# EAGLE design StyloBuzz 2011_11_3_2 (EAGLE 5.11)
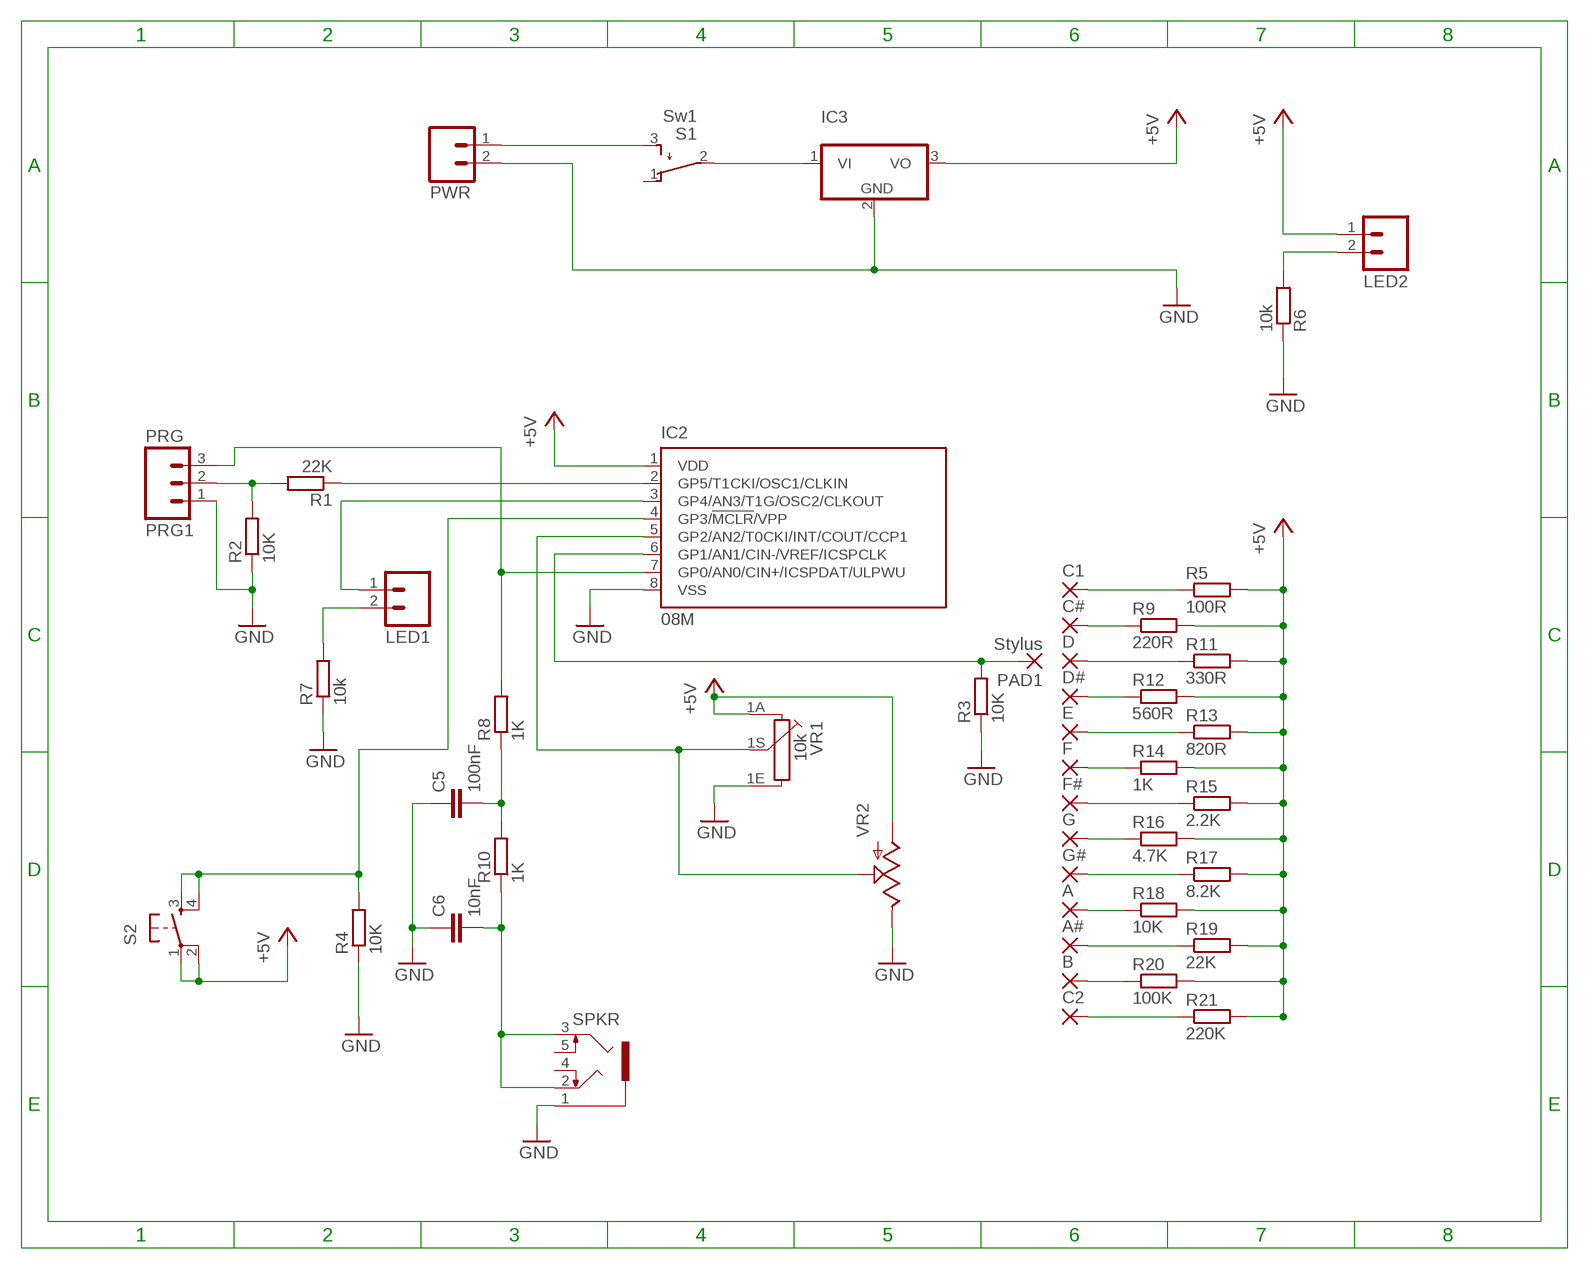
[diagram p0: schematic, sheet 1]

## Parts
A  1,6/0,8  [1,6/0,8]
A#  1,6/0,8  [1,6/0,8]
B  1,6/0,8  [1,6/0,8]
C1  1,6/0,8  [1,6/0,8]
C2  1,6/0,8  [1,6/0,8]
C5  100nF  C5/2.5  [C5B2.5]
C6  10nF  C5/2.5  [C5B2.5]
C#  1,6/0,8  [1,6/0,8]
D  1,6/0,8  [1,6/0,8]
D#  1,6/0,8  [1,6/0,8]
E  1,6/0,8  [1,6/0,8]
F  1,6/0,8  [1,6/0,8]
F#  1,6/0,8  [1,6/0,8]
G  1,6/0,8  [1,6/0,8]
G#  1,6/0,8  [1,6/0,8]
IC2  08M  PIC12F683P  [DIL8]
IC3  786TV  [TO220V]
LED1  M02  [02P]
LED2  M02  [02P]
PAD1  Stylus  3,81/1,4  [3,81/1,4]
PRG  PRG1  M03  [03P]
PWR  M02  [02P]
R1  22K  R-EU_0207/10  [0207/10]
R2  10K  R-EU_0207/10  [0207/10]
R3  10K  R-EU_0207/10  [0207/10]
R4  10K  R-EU_0207/10  [0207/10]
R5  100R  R-EU_0207/10  [0207/10]
R6  10k  R-EU_0207/10  [0207/10]
R7  10k  R-EU_0207/10  [0207/10]
R8  1K  R-EU_0207/10  [0207/10]
R9  220R  R-EU_0207/10  [0207/10]
R10  1K  R-EU_0207/10  [0207/10]
R11  330R  R-EU_0207/10  [0207/10]
R12  560R  R-EU_0207/10  [0207/10]
R13  820R  R-EU_0207/10  [0207/10]
R14  1K  R-EU_0207/10  [0207/10]
R15  2.2K  R-EU_0207/10  [0207/10]
R16  4.7K  R-EU_0207/10  [0207/10]
R17  8.2K  R-EU_0207/10  [0207/10]
R18  10K  R-EU_0207/10  [0207/10]
R19  22K  R-EU_0207/10  [0207/10]
R20  100K  R-EU_0207/10  [0207/10]
R21  220K  R-EU_0207/10  [0207/10]
S1  Sw1  TL32YO  [TL3XYO]
S2  TAC_SWITCHPTH  [TACTILE-PTH]
SPKR  1503_09  [1503_09]
VR1  10k  PC16S  [PC16S]
VR2  POT  [ALPS_POT]

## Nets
+5V: IC2.1(VDD) IC3.3(VO) LED2.1 R5.2 R9.2 R11.2 R12.2 R13.2 R14.2 R15.2 R16.2 R17.2 R18.2 R19.2 R20.2 R21.2 S2.1 S2.2 VR1.1A VR2.P$3(A)
N$1: PWR.1 S1.3(S)
N$2: IC3.1(VI) S1.2(P)
N$3: IC2.2(GP5/T1CKI/OSC1/CLKIN) R1.1
N$4: C1.1(P) R5.1
N$5: IC2.4(GP3/!MCLR!/VPP) R4.2 S2.3 S2.4
N$6: IC2.7(GP0/AN0/CIN+/ICSPDAT/ULPWU) PRG.3 R8.2
N$7: IC2.3(GP4/AN3/T1G/OSC2/CLKOUT) LED1.1
N$8: C#.1(P) R9.1
N$9: IC2.6(GP1/AN1/CIN-/VREF/ICSPCLK) PAD1.1(P) R3.2
N$10: LED1.2 R7.2
N$11: C5.2 R8.1 R10.2
N$12: C6.2 R10.1 SPKR.2 SPKR.3
N$13: IC2.5(GP2/AN2/T0CKI/INT/COUT/CCP1) VR1.1S VR2.P$2(S)
N$14: D.1(P) R11.1
N$15: D#.1(P) R12.1
N$16: LED2.2 R6.2
N$17: E.1(P) R13.1
N$18: F.1(P) R14.1
N$19: F#.1(P) R15.1
N$20: G.1(P) R16.1
N$21: G#.1(P) R17.1
N$22: A.1(P) R18.1
N$23: A#.1(P) R19.1
N$24: B.1(P) R20.1
N$25: C2.1(P) R21.1
N$26: PRG.2 R1.2 R2.2
N$28: C5.1 C6.1 IC2.8(VSS) IC3.2(GND) PRG.1 PWR.2 R2.1 R3.1 R4.1 R6.1 R7.1 SPKR.1 VR1.1E VR2.P$1(E) ; supply symbol labelled GND
Unconnected: S1.1(O) SPKR.4 SPKR.5

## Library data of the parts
A A# B C1 C2 C# D D# E F F# G G# = wirepad:1,6/0,8: THROUGH-HOLE PAD
C5 C6 = capacitor-wima:C: CAPACITOR
IC2 = microchip:PIC12F683: 8-Pin Flash-Based, 8-Bit CMOS Microcontrollers with nanoWatt Technology Source: http://ww1.microchip.com/downloads/en/DeviceDoc/41211D_.pdf; MF: MICROCHIP; MPN: PIC12F683-I/P; OC_FARNELL: 9759034; OC_NEWARK: 89H0442
IC3 = linear:78*: Positive VOLTAGE REGULATOR Source: http://cache.national.com/ds/LM/LM78L05.pdf http://www.fairchildsemi.com/ds/LM/LM7805.pdf
LED1 LED2 PWR = con-amp-quick:M02: AMP QUICK CONNECTOR; OC_FARNELL: unknown; OC_NEWARK: unknown
PAD1 = wirepad:3,81/1,4: THROUGH-HOLE PAD
PRG = con-amp-quick:M03: AMP QUICK CONNECTOR; OC_FARNELL: unknown; OC_NEWARK: unknown
R1-R21 = resistor2:R-EU_: RESISTOR, European symbol
S1 = switch:TL32YO: TINY SWITCH ON - MOM Source: http://www2.produktinfo.conrad.com/datenblaetter/700000-724999/705152-da-01-de-Subminiaturschalter_TL_36YO.pdf
S2 = SparkFun:TAC_SWITCH: Momentary Switch Button commonly used for reset or general input. Spark Fun Electronics SKU : COM-00097
SPKR = con-lumberg:1503_09: Jack connectors according to JISC 6560, 3.5 mm Klinkeneinbaukupplung nach JISC 6560, 3,5 mm, 3-polig/ stereo, abgewinkelte Ausführung, mit 2 Öffnern und Lötaugen, für Leiterplatten Rückseitenmontage Source: http://www.lumberg.com/Produkte/PDFs/1503_09.pdf; OC_FARNELL: 1243244; OC_NEWARK: unknown
VR1 = piher:PC16S: POTENTIOMETER single carbon potentiometer, 16 mm, S3ROH; OC_FARNELL: 4452940; OC_NEWARK: unknown
VR2 = SparkFun:POT

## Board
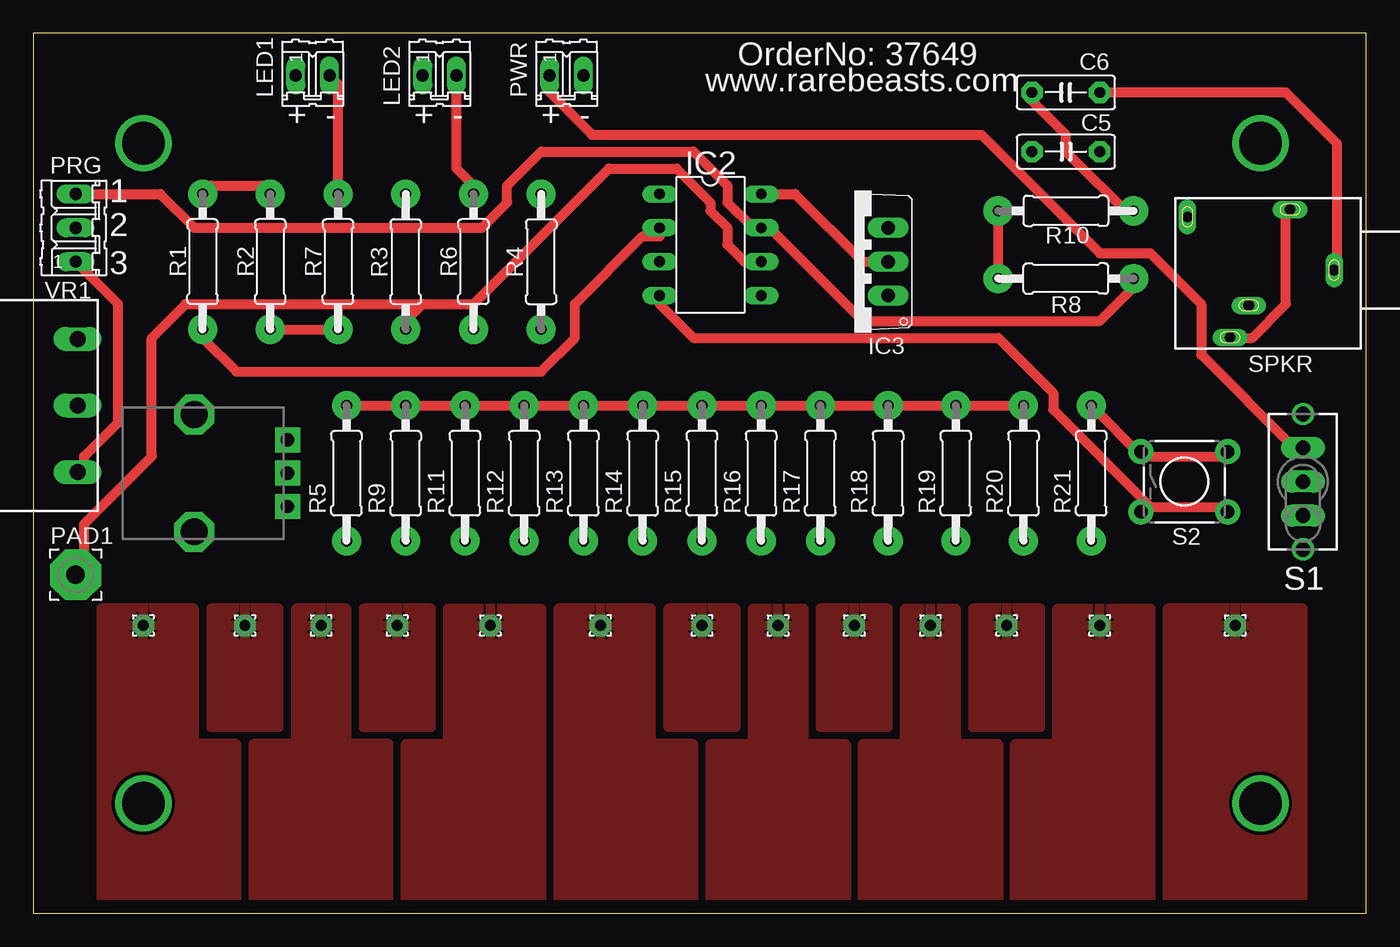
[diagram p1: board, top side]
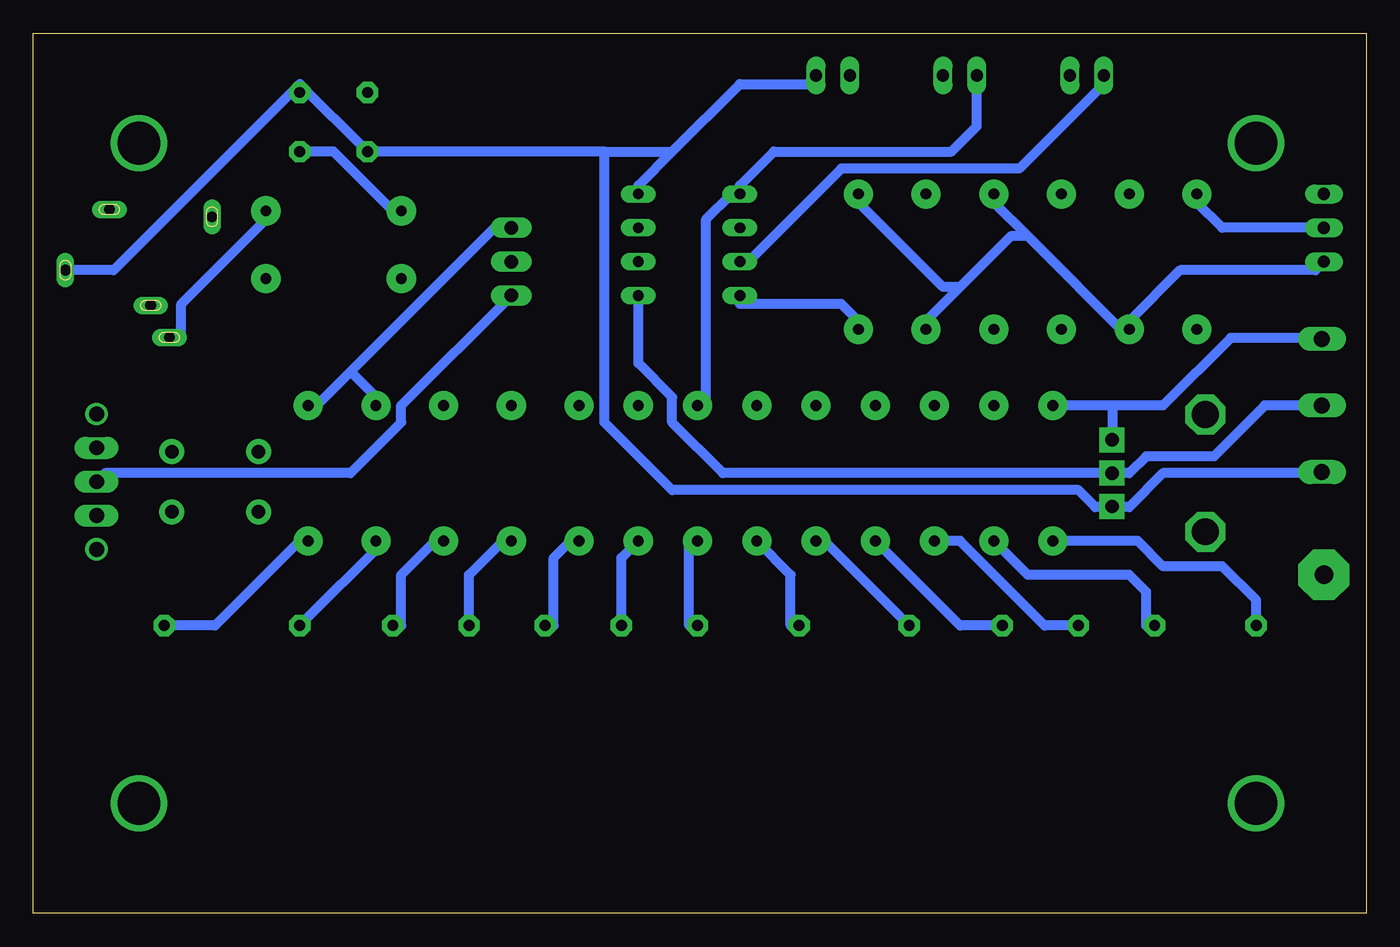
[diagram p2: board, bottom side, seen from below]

Size 100 x 66.03 mm. Coordinates in mm from the lower left corner, seen from the top.
Outline: 0,0 100,0 100,66.03 0,66.03 0,0
Copper layers (1*16): Top 0.035mm / dielectric 1.5mm / Bottom 0.035mm
Design rules "default *": minimum track width 30mil, minimum drill 24mil, track to track 8mil, track to pad 8mil, pad to pad 8mil, via to via 8mil, smd to smd 8mil, copper to edge 40mil, drill to drill 8mil, minimum pad ring 10mil, minimum via ring 8mil, stop-mask expansion 4mil, vias tented up to drill 0mil, thermal gap 10mil

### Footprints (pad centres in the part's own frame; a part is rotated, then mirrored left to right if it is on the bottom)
1,6/0,8 = drill 0.813 pad 1.6 octagon: 1 0,0
C5B2.5 = drill 0.813 pad 1.6 octagon: 1 -2.54,0; 2 2.54,0
DIL8 = drill 0.813 long: 1 -3.81,-3.81; 2 -1.27,-3.81; 3 1.27,-3.81; 4 3.81,-3.81; 5 3.81,3.81; 6 1.27,3.81; 7 -1.27,3.81; 8 -3.81,3.81
TO220V = drill 1.016 long: 1 -2.54,-2.54; 2 0,-2.54; 3 2.54,-2.54
02P = drill 0.914 long: 1 -1.27,0; 2 1.27,0
3,81/1,4 = drill 1.397 pad 3.81 octagon: 1 0,0
03P = drill 0.914 long: 1 -2.54,0; 2 0,0; 3 2.54,0
0207/10 = drill 0.813 pad 2.184 round: 1 -5.08,0; 2 5.08,0
TL3XYO = drill 1.1 pad 1.422 long: 1 -2.54,0; 2 0,0; 3 2.54,0 | drill 1.1 pad 1.676 round: M1 -5.08,0; M2 5.08,0
TACTILE-PTH = drill 1.016 pad 1.88 round: 1 -3.251,2.261; 2 3.251,2.261; 3 -3.251,-2.261; 4 3.251,-2.261
1503_09 = drill 0.8 pad 1.2 long: 1 0,-2.1; 2 -4.55,-5.4; 3 5.05,-9.9; 4 -4,-13.1; 5 2.65,-8.5
PC16S = drill 1.2 long: 1A -5,6.5; 1E 5,6.5; 1S 0,6.5
ALPS_POT = drill 1 pad 1.88 square: P$1 7,-2.5; P$2 7,0; P$3 7,2.5 | drill 2 octagon: P$4 0,-4.4; P$5 0,4.4

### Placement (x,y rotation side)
A  67.31,21.59 0 top
A#  73.03,21.59 0 top
B  80.01,21.59 0 top
C1  8.26,21.59 0 top
C2  90.17,21.59 0 top
C5  77.47,57.15 0 top
C6  77.47,61.59 180 top
C#  15.88,21.59 0 top
D  21.59,21.59 0 top
D#  27.3,21.59 0 top
E  34.29,21.59 0 top
F  42.55,21.59 0 top
F#  50.16,21.59 0 top
G  55.88,21.59 0 top
G#  61.59,21.59 0 top
IC2  50.8,50.16 270 top
IC3  61.59,48.9 90 top
LED1  20.95,62.87 0 top
LED2  30.48,62.87 0 top
PAD1  3.17,25.4 0 top
PRG  3.17,51.44 90 top
PWR  40.01,62.87 0 top
R1  12.7,48.9 90 top
R2  17.78,48.9 90 top
R3  27.94,48.9 270 top
R4  38.1,48.9 270 top
R5  23.5,33.02 90 top
R6  33.02,48.9 90 top
R7  22.86,48.9 90 top
R8  77.47,47.62 0 top
R9  27.94,33.02 90 top
R10  77.47,52.7 180 top
R11  32.38,33.02 90 top
R12  36.83,33.02 90 top
R13  41.27,33.02 90 top
R14  45.72,33.02 90 top
R15  50.16,33.02 90 top
R16  54.61,33.02 90 top
R17  59.05,33.02 90 top
R18  64.14,33.02 90 top
R19  69.22,33.02 90 top
R20  74.3,33.02 90 top
R21  79.38,33.02 90 top
S1  95.25,32.38 90 top
S2  86.36,32.38 0 top
SPKR  99.69,48.26 270 top
VR1  -3.17,38.1 270 top
VR2  12.06,33.02 0 top

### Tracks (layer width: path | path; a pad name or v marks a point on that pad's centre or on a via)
+5V
  Top 0.762: R5.2 R9.2 R11.2 R12.2 R13.2 R14.2 R15.2 R16.2 R17.2 R18.2 R19.2 R20.2 | S2.2 89.53,34.29 83.82,34.29 S2.1 83.19,34.29 R21.2
  Bottom 0.762: VR1.1A 3.81,43.18 10.16,43.18 15.24,38.1 19.05,38.1 | 19.05,38.1 R5.2 | IC3.3 65.41,51.44 76.2,40.64 | 76.2,40.64 78.74,38.1 R21.2 | R15.2 49.53,38.1 49.53,52.07 47.62,53.98 IC2.1 46.99,54.61 44.45,57.15 31.11,57.15 29.21,59.05 LED2.1 | 76.2,40.64 73.66,38.1 R20.2 | 19.05,38.1 19.05,35.56 VR2.P$3
N$1
  Top 0.762: PWR.1 38.73,61.59 41.91,58.42 71.12,58.42 80.01,49.53 83.82,49.53 87.63,45.72 87.63,41.91 94.61,34.92 S1.3
N$2
  Bottom 0.762: IC3.1 72.39,38.1 72.39,36.83 76.2,33.02 94.61,33.02 S1.2
N$3
  Top 0.762: IC2.2 46.99,50.8 45.72,50.8 40.64,45.72 40.64,43.18 38.1,40.64 15.24,40.64 12.7,43.18 R1.1
N$4
  Bottom 0.762: C1.1 8.26,23.5 10.79,26.04 15.24,26.04 17.14,27.94 R5.1
  pour Top (isolate 0.254): 5.08,22.86 5.08,0 15.24,0 15.24,12.7 12.06,12.7 12.06,22.86
N$5
  Top 0.762: 83.82,30.48 88.9,30.48 S2.4 | 83.82,30.48 76.52,37.78 76.52,39.05 72.39,43.18 49.53,43.18 46.99,45.72 IC2.4 | 83.82,30.48 S2.3
  Bottom 0.762: IC2.4 46.99,45.72 39.37,45.72 38.1,44.45 R4.2
N$6
  Top 0.762: R8.2 82.55,46.99 80.01,44.45 62.23,44.45 55.24,51.44 IC2.7 53.98,51.44 52.07,53.34 52.07,54.61 49.53,57.15 38.1,57.15 35.56,54.61 35.56,53.34 33.66,51.44 12.06,51.44 9.53,53.98 PRG.3
N$7
  Bottom 0.762: IC2.3 46.35,48.9 39.37,55.88 26.04,55.88 19.68,62.23 LED1.1
N$8
  Bottom 0.762: R9.1 25.4,25.4 17.78,25.4 16.51,24.13 16.51,21.59 C#.1
  pour Top (isolate 0.254): 13.34,22.86 13.34,13.97 18.41,13.97 18.41,22.86
N$9
  Top 0.762: 29.21,45.72 33.02,45.72 43.18,55.88 48.26,55.88 50.8,53.34 50.8,52.7 52.07,51.44 52.07,50.16 53.34,48.9 IC2.6 | 29.21,45.72 27.94,44.45 R3.2 | 29.21,45.72 11.43,45.72 8.89,43.18 8.89,34.29 3.81,29.21 3.81,25.4 PAD1.1
N$10
  Top 0.762: LED1.2 22.86,62.23 R7.2
N$11
  Top 0.762: R8.1 R10.2
  Bottom 0.762: C5.2 77.47,57.15 72.39,52.07 R10.2
N$12
  Top 0.762: SPKR.2 93.98,52.7 93.98,45.72 91.44,43.18 90.17,43.18 SPKR.3 | C6.2 74.93,60.96 77.47,58.42 77.47,57.15 82.55,52.07 R10.1
  Bottom 0.762: SPKR.3 88.9,43.18 88.9,45.72 82.55,52.07 R10.1
N$13
  Bottom 0.762: IC2.5 54.61,41.27 52.07,38.73 52.07,36.83 48.26,33.02 VR2.P$2 17.78,33.02 16.51,34.29 11.43,34.29 7.62,38.1 VR1.1S
N$14
  Bottom 0.762: D.1 24.13,21.59 30.48,27.94 R11.1
  pour Top (isolate 0.254): 16.51,0 26.67,0 26.67,12.7 23.5,12.7 23.5,22.86 19.68,22.86 19.68,12.7 16.51,12.7
N$15
  Bottom 0.762: R12.1 30.48,21.59 D#.1
  pour Top (isolate 0.254): 24.77,22.86 24.77,13.97 29.84,13.97 29.84,22.86
N$16
  Top 0.762: LED2.2 31.75,55.88 33.02,54.61 R6.2
N$17
  Bottom 0.762: E.1 40.64,27.94 R13.1
  pour Top (isolate 0.254): 31.11,22.86 38.1,22.86 38.1,0 27.94,0 27.94,12.7 31.11,12.7
N$18
  Bottom 0.762: R14.1 43.18,25.4 43.18,21.59 F.1
  pour Top (isolate 0.254): 39.37,22.86 39.37,0 49.53,0 49.53,12.7 46.35,12.7 46.35,22.86
N$19
  Bottom 0.762: F#.1 50.8,21.59 50.8,27.94 R15.1
  pour Top (isolate 0.254): 47.62,22.86 47.62,13.97 52.7,13.97 52.7,22.86
N$20
  Bottom 0.762: G.1 55.88,26.67 R16.1
  pour Top (isolate 0.254): 53.98,22.86 57.78,22.86 57.78,12.7 60.96,12.7 60.96,0 50.8,0 50.8,12.7 53.98,12.7
N$21
  Bottom 0.762: G#.1 60.96,21.59 60.96,26.67 59.69,27.94 R17.1
  pour Top (isolate 0.254): 59.05,22.86 59.05,13.97 64.14,13.97 64.14,22.86
N$22
  Bottom 0.762: A.1 67.31,25.4 64.77,27.94 R18.1
  pour Top (isolate 0.254): 65.41,22.86 69.22,22.86 69.22,12.7 72.39,12.7 72.39,0 62.23,0 62.23,12.7 65.41,12.7
N$23
  Bottom 0.762: A#.1 72.39,21.59 72.39,25.4 69.85,27.94 R19.1
  pour Top (isolate 0.254): 70.48,22.86 70.48,13.97 75.56,13.97 75.56,22.86
N$24
  Bottom 0.762: B.1 73.66,27.94 R20.1
  pour Top (isolate 0.254): 76.83,22.86 83.82,22.86 83.82,0 73.66,0 73.66,12.7 76.83,12.7
N$25
  Bottom 0.762: C2.1 86.36,21.59 80.01,27.94 R21.1
  pour Top (isolate 0.254): 85.09,0 95.25,0 95.25,22.86 85.09,22.86
N$26
  Top 0.762: R2.2 17.14,54.61 13.34,54.61 R1.2
  Bottom 0.762: PRG.2 10.79,51.44 12.7,53.34 R1.2
N$27  (via drill 3.2 pad 3.81)
  other vias: 92.08,57.78
N$28
  Top 0.762: 97.79,48.26 97.79,57.78 93.98,61.59 C6.1 | R2.1 R7.1 | VR1.1E 3.81,33.02 3.81,34.29 6.35,36.83 6.35,45.72 PRG.1 | IC2.8 57.15,53.98 62.23,48.9 IC3.2
  Bottom 0.762: 19.05,30.48 17.78,30.48 15.24,33.02 3.81,33.02 VR1.1E | PRG.1 3.81,48.26 13.97,48.26 17.78,44.45 R2.1 17.78,43.18 25.4,50.8 | 25.4,50.8 27.94,53.34 R3.1 | 30.48,46.99 26.67,50.8 25.4,50.8 | 30.48,46.99 33.02,44.45 R6.1 | 30.48,46.99 31.75,46.99 38.1,53.34 R4.1 | 80.01,62.23 93.98,48.26 SPKR.1 97.79,48.26 | 80.01,62.23 C5.1 57.15,57.15 | 80.01,62.23 C6.1 | 52.07,57.15 54.61,54.61 IC2.8 | 52.07,57.15 46.99,62.23 41.91,62.23 PWR.2 | 57.15,57.15 52.07,57.15 | 19.05,30.48 20.32,30.48 21.59,31.75 52.07,31.75 57.15,36.83 57.15,57.15 | 19.05,30.48 VR2.P$1
N$30  (via drill 3.2 pad 3.81)
  other vias: 8.26,8.26
N$31  (via drill 3.2 pad 3.81)
  other vias: 8.26,57.78
N$32  (via drill 3.2 pad 3.81)
  other vias: 92.08,8.26

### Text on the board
tNames: OrderNo: 37649 | www.rarebeasts.com | + | - | + | - | + | - | 1 | 2 | 3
